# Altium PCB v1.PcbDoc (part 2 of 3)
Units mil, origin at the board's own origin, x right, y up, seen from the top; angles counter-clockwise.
Board outline 2610 x 5109 mil, 2 copper layers (Top Layer, Bottom Layer), stack 62 mil thick; 307 components, 181 nets, 763 pads, 1057 vias.
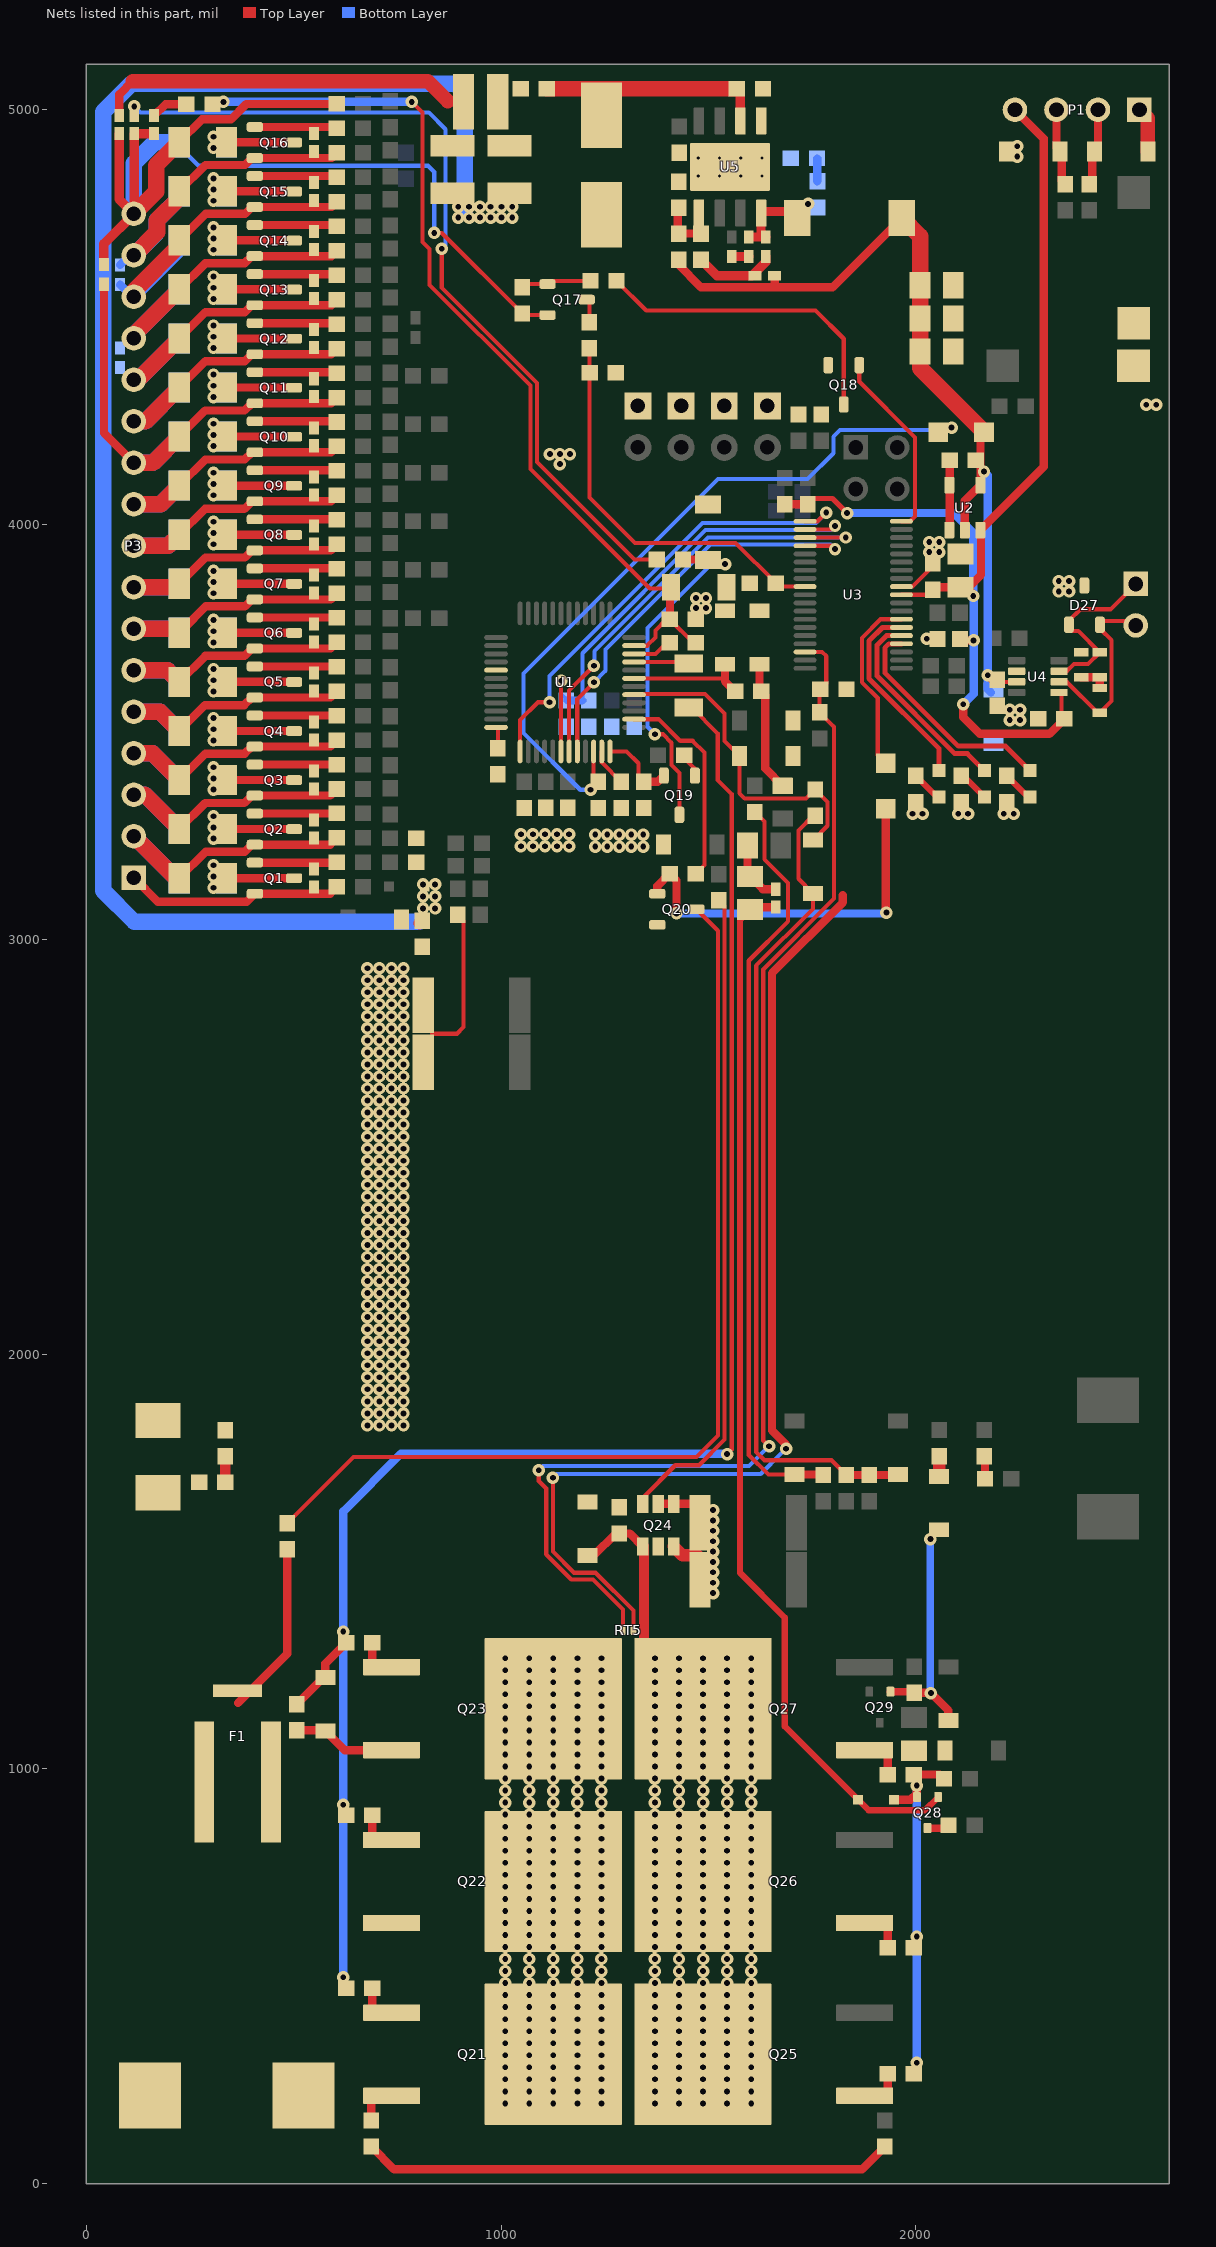
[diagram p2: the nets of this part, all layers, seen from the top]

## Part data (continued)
L2: "Inductor, Shielded Drum Core, Metal Composite, 68 μH, 0.87 A, 0.239 ohm, SMD", Manufacturer="Wurth Elektronik", Supplier Part Number 1=732-1201-1-ND, Value1="0.239 ohm", Value2=0.87A, ValueDisplayed=68μH
L3 L4 L5 L6 L7 L8: "Ferrite Bead, 600 ohm @ 100 MHz, 0.2 A, 0603", Manufacturer="Wurth Elektronik", Supplier Part Number 1=732-1583-1-ND, Value1="0.45 ohm", Value2=0.2A, ValueDisplayed="600 ohm"
Logo1: library part CMP-0074836-1, "IEC 61010-1 Caution Warning"
Logo2: library part CMP-0074847-1, "FCC_disclaimer"
Logo3: library part CMP-0074769-1
P1: "Header, 4-Pin"
P2: "Header, 2-Pin, Dual row"
P3: "Header, 17-Pin"
P4: "Header, 2-Pin"
Q1 Q2 Q3 Q4 Q5 Q6 Q7 Q8 Q9 Q10 Q11 Q12 Q13 Q14 Q15 Q16: "MOSFET, N-CH, 20 V, 2.8 A, AEC-Q101, SOT-23", Alternate Manufacturer=None, Manufacturer="Diodes Inc.", Supplier Part Number 1=DMG2302UK-7DICT-ND, Value1="0.09 ohm", Value2="1.4 nC"
Q17: "MOSFET, P-CH, -100 V, -0.6 A, SOT-23", Alternate Manufacturer=None, Manufacturer="Diodes Inc.", Supplier Part Number 1=ZXMP10A13FCT-ND, Value1="1 ohm", Value2="3.5 nC"
Q18: "MOSFET, N-CH, 100 V, 0.17 A, SOT-23", Alternate Manufacturer=None, Manufacturer="Fairchild Semiconductor", Supplier Part Number 1=BSS123NCT-ND, Value1="10 ohm", Value2="1.8 nC"
Q19: library part "ZXTN25100BFHTA, Diodes Inc.", "Transistor, NPN, 100 V, 3 A, AEC-Q101, SOT-23", Manufacturer="Diodes Inc.", Supplier Part Number 1=ZXTN25100BFHCT-ND, Value1="3 A", Value2=300
Q20: "MOSFET, N-CH, 100 V, 1.4 A, SOT-23", Alternate Manufacturer=None, Manufacturer="Diodes Inc.", Supplier Part Number 1=DMN10H220L-7DICT-ND, Value1="0.25 ohm", Value2="4.1 nC"
Q21 Q22 Q23 Q25 Q26 Q27: "MOSFET, N-CH, 100 V, 200 A, KTT0002A (TO-263-2)", Alternate Manufacturer=None, Manufacturer="Texas Instruments", Supplier Part Number 1=296-41136-1-ND, Value1="? ohm", Value2="118 nC"
Q24: "MOSFET, P-CH, -80 V, -2.1 A, SSOT-6", Alternate Manufacturer=None, Manufacturer="Fairchild Semiconductor", Supplier Part Number 1=FDC3535CT-ND, Value1="0.233 ohm", Value2="14 nC"
Q28: "MOSFET, P-CH, -20 V, -0.82 A, SOT-323", Alternate Manufacturer=None, Manufacturer="Diodes Inc.", Supplier Part Number 1=DMG1013UW-7DICT-ND, Value1="0.75 ohm", Value2="0.622 nC"
Q29: "MOSFET, N-CH, 60 V, 0.115 A, SOT-323", Alternate Manufacturer=None, Manufacturer="Diodes Inc.", Supplier Part Number 1=2N7002W-FDICT-ND, Value1="7.5 ohm", Value2="? nC"
R1 R3 R5 R7 R9 R11 R13 R15 R36 R38 R40 R42 R44: "RES, 80.6, 1%, 0.25 W, 1206", Manufacturer=Vishay-Dale, Power_W=0.25, Supplier Part Number 1=541-80.6FCT-ND, TempCo="100 ppm/C", Tolerance_%=1, Value1=1%, Value2=0.25W, Value_Code=80R6
R2 R4 R6 R8 R10 R12 R14 R16 R37 R39 R41 R43 R45 R72 R73 R74 R75 R76 R77: "RES, 80.6, 1%, 0.25 W, 1206", Manufacturer=Vishay-Dale, Power_W=0.25, Supplier Part Number 1=541-80.6FCT-ND, TempCo="100 ppm/C", Tolerance_%=1, Value1=1%, Value2=0.25W, Value_Code=80R6, ValueDisplayed=80.6
R17 R19 R21 R23 R25 R27 R29 R31 R33 R52 R54 R56 R58 R60 R61 R79 R81 R83 R87 R88 R93 R95 R96 R97 R98 R105 R106 R107 R130: "RES, 100, 1%, 0.1 W, 0603", Manufacturer=Vishay-Dale, Power_W=0.1, Supplier Part Number 1=541-100HCT-ND, TempCo="100 ppm/C", Tolerance_%=1, Value1=1%, Value2=0.1W, Value_Code=100R, ValueDisplayed=100
R18 R20 R22 R24 R26 R28 R30 R32 R51 R53 R55 R57 R59 R78 R80 R82 R84 R89 R90 R102 R103 R136: "RES, 10 k, 5%, 0.1 W, 0603", Manufacturer=Vishay-Dale, Power_W=0.1, Supplier Part Number 1=541-10KGCT-ND, TempCo="200 ppm/C", Tolerance_%=5, Value1=5%, Value2=0.1W, Value_Code=10k0, ValueDisplayed=10k
R34 R46 R47 R71 R117: "RES, 0, 5%, 0.063 W, 0402", Manufacturer=Vishay-Dale, Power_W=0.063, Supplier Part Number 1=541-0.0JCT-ND, TempCo="200 ppm/C", Tolerance_%=5, Value1=5%, Value2=0.063W, Value_Code=0000, ValueDisplayed=0
R35 R48 R49 R50 R62 R63 R64 R65 R66 R67 R68 R69 R70 R111 R115: "RES, 0, 5%, 0.1 W, 0603", Manufacturer=Vishay-Dale, Power_W=0.1, Supplier Part Number 1=541-0.0GCT-ND, TempCo="200 ppm/C", Tolerance_%=5, Value1=5%, Value2=0.1W, Value_Code=0000, ValueDisplayed=0
R85: "RES, 13.3 k, 0.5%, 0.1 W, 0603", Manufacturer="Yageo America", Power_W=0.1, TempCo="50 ppm/C", Tolerance_%=0.5, Value1=0.5%, Value2=0.1W, Value_Code=13k3, ValueDisplayed=13.3k
R86: "RES, 665 k, 0.5%, 0.1 W, 0603", Manufacturer="Yageo America", Power_W=0.1, TempCo="50 ppm/C", Tolerance_%=0.5, Value1=0.5%, Value2=0.1W, Value_Code=665k
R91: "RES, 3.3 M, 5%, 0.1 W, 0603", Manufacturer=Vishay-Dale, Power_W=0.1, Supplier Part Number 1=541-3.3MGCT-ND, TempCo="200 ppm/C", Tolerance_%=5, Value1=5%, Value2=0.1W, Value_Code=3M30, ValueDisplayed=3.3M
R92 R126: "RES, 1.0 M, 5%, 0.1 W, 0603", Manufacturer=Vishay-Dale, Power_W=0.1, Supplier Part Number 1=541-1.0MGCT-ND, TempCo="200 ppm/C", Tolerance_%=5, Value1=5%, Value2=0.1W, Value_Code=1M00, ValueDisplayed=1.0M
R94: "RES, 249, 1%, 0.1 W, 0603", Manufacturer="Yageo America", Power_W=0.1, Supplier Part Number 1=311-249HRCT-ND, TempCo="200 ppm/C", Tolerance_%=1, Value1=1%, Value2=0.1W, Value_Code=249R, ValueDisplayed=249
R99 R100 R101: "RES, 470, 1%, 0.1 W, 0603", Manufacturer="Yageo America", Power_W=0.1, Supplier Part Number 1=311-470HRCT-ND, TempCo="200 ppm/C", Tolerance_%=1, Value1=1%, Value2=0.1W, Value_Code=470R, ValueDisplayed=470
R104: "RES, 47.0 k, 1%, 0.1 W, 0603", Manufacturer="Yageo America", Power_W=0.1, Supplier Part Number 1=311-47.0KHRCT-ND, TempCo="200 ppm/C", Tolerance_%=1, Value1=1%, Value2=0.1W, Value_Code=47k0, ValueDisplayed=47.0k
R108: "RES, 10.0 k, 1%, 0.1 W, 0603", Manufacturer=Vishay-Dale, Power_W=0.1, Supplier Part Number 1=541-10.0KHCT-ND, TempCo="100 ppm/C", Tolerance_%=1, Value1=1%, Value2=0.1W, Value_Code=10k0, ValueDisplayed=10.0k
R109 R110: "RES, 60.4, 1%, 0.1 W, 0603", Manufacturer="Yageo America", Power_W=0.1, Supplier Part Number 1=311-60.4HRCT-ND, TempCo="200 ppm/C", Tolerance_%=1, Value1=1%, Value2=0.1W, Value_Code=60R4, ValueDisplayed=60.4
R112 R113: "RES, 0.002, 1%, 2 W, 2512", Manufacturer="Stackpole Electronics Inc", Power_W=2, Supplier Part Number 1=CSNL2512FT2L00CT-ND, TempCo="50 ppm/C", Tolerance_%=1, Value1=1%, Value2=2W, Value_Code=2L000, ValueDisplayed=0.002
R114 R139: "RES, 5.1 k, 5%, 0.1 W, 0603", Manufacturer=Vishay-Dale, Power_W=0.1, Supplier Part Number 1=541-5.1KGCT-ND, TempCo="200 ppm/C", Tolerance_%=5, Value1=5%, Value2=0.1W, Value_Code=5k10, ValueDisplayed=5.1k
R116: "RES, 82.5 k, 1%, 0.1 W, 0603", Manufacturer=Vishay-Dale, Power_W=0.1, Supplier Part Number 1=541-82.5KHCT-ND, TempCo="100 ppm/C", Tolerance_%=1, Value1=1%, Value2=0.1W, Value_Code=82k5, ValueDisplayed=82.5k
R118: library part RC0603FR-07499KL, "RES, 499 k, 1%, 0.1 W, 0603", Manufacturer="Yageo America", Power_W=0.1, Supplier Part Number 1=311-499KHRCT-ND, TempCo="200 ppm/C", Tolerance_%=1, Value1=1%, Value2=0.1W, Value_Code=499k
R119: library part CRCW0402523KFKED, "RES, 523 k, 1%, 0.063 W, 0402", Manufacturer=Yageo, Power_W=0.063, Supplier Part Number 1=541-523KLCT-ND, TempCo="100 ppm/C", Tolerance_%=1, Value1=1%, Value2=0.063W, Value_Code=523k
R120: "RES, 63.4 k, 1%, 0.1 W, 0603", Manufacturer=Vishay-Dale, Power_W=0.1, Supplier Part Number 1=541-63.4KHCT-ND, TempCo="100 ppm/C", Tolerance_%=1, Value1=1%, Value2=0.1W, Value_Code=63k4, ValueDisplayed=63.4k
R121: "RES, 200 k, 1%, 0.1 W, 0603", Manufacturer=Vishay-Dale, Power_W=0.1, Supplier Part Number 1=541-200KHCT-ND, TempCo="100 ppm/C", Tolerance_%=1, Value1=1%, Value2=0.1W, Value_Code=200k
R122: "RES, 200, 1%, 0.1 W, 0603", Manufacturer=Vishay-Dale, Power_W=0.1, Supplier Part Number 1=541-200HCT-ND, TempCo="100 ppm/C", Tolerance_%=1, Value1=1%, Value2=0.1W, Value_Code=200R, ValueDisplayed=200
R123: "RES, 499, 1%, 0.25 W, 1206", Manufacturer=Panasonic, Power_W=0.25, Supplier Part Number 1=P499FCT-ND, TempCo="100 ppm/C", Tolerance_%=1, Value1=1%, Value2=0.25W, Value_Code=499R, ValueDisplayed=499
R124 R131 R137: "RES, 10 M, 5%, 0.1 W, 0603", Manufacturer=Vishay-Dale, Power_W=0.1, Supplier Part Number 1=541-10MGCT-ND, TempCo="200 ppm/C", Tolerance_%=5, Value1=5%, Value2=0.1W, Value_Code=10M0, ValueDisplayed=10M
R125 R138 R140: "RES, 49.9 k, 0.1%, 0.1 W, 0603", Manufacturer="Yageo America", Power_W=0.1, TempCo="25 ppm/C", Value1=0.1%, Value2=0.1W, Value_Code=49k9, ValueDisplayed=49.9k
R127 R128: library part CRCW2512604RFKEG, "RES SMD 510 OHM 5% 1W 2512", Manufacturer=Yageo, Power_W=1, Supplier Part Number 1=541-604AFCT-ND, TempCo="100 ppm/C", Value1=5%, Value2=1W, Value_Code=510R, ValueDisplayed=510
R129: library part CRCW080556K0JNEA, "RES, 56 k, 5%, 0.125 W, 0805", Manufacturer=Yageo, Power_W=0.125, Supplier Part Number 1=541-56KACT-ND, TempCo="200 ppm/C", Tolerance_%=5, Value1=5%, Value2=0.125W, Value_Code=56k0, ValueDisplayed=56k
R132 R133 R134: "RES, 511, 1%, 0.125 W, 0805", Manufacturer=Vishay-Dale, Power_W=0.125, Supplier Part Number 1=541-511CCT-ND, TempCo="100 ppm/C", Tolerance_%=1, Value1=1%, Value2=0.125W, Value_Code=511R, ValueDisplayed=511
R135: "RES, 511, 1%, 0.1 W, 0603", Manufacturer=Vishay-Dale, Power_W=0.1, Supplier Part Number 1=541-511HCT-ND, TempCo="100 ppm/C", Tolerance_%=1, Value1=1%, Value2=0.1W, Value_Code=511R, ValueDisplayed=511
R141 R142: "RES, 20 k, 5%, 0.1 W, 0603", Manufacturer=Vishay-Dale, Power_W=0.1, Supplier Part Number 1=541-20KGCT-ND, TempCo="200 ppm/C", Tolerance_%=5, Value1=5%, Value2=0.1W, Value_Code=20k0, ValueDisplayed=20k
RT1 RT2 RT3 RT4: library part 103AT-2, "Thermistor NTC, 10.0k ohm, 1%, Disc, 5x8.4 mm", Manufacturer=Cantherm, Power_W=0.01, Supplier Part Number 1=954-103AT-2, Tolerance_%=1
RT5: library part CMP-0084566-1, "Thermistor, DEC0002A (X1SON-2)", Alternate Manufacturer="Texas Instruments", Alternate PartNumber=TMP6131DECT
S1 S2: "Switch, Tactile, SPST-NO, 0.05A, 12V, SMD", CurrentRating_mA=50, Manufacturer="C&K Components", Supplier Part Number 1=CKN10388CT-ND
U1: library part CMP-0084230-1, "Multicell Battery Monitor and Protection Family, PFB0048A (TQFP-48)", Alternate Manufacturer="Texas Instruments", Alternate PartNumber=bq76952PFBT
U2: "Single Output LDO, 150 mA, Fixed 3.3 V Output, 2.5 to 24 V Input, with Ultra-Low IQ, 5-pin SOT-23 (DBV), -40 to 125 degC, Green (RoHS & no Sb/Br)", Alternate Manufacturer="Texas Instruments", Alternate PartNumber=Equivalent, Supplier Part Number 1=296-27946-2-ND
U3: library part CMP-0084060-1, "24MHz 105C ULP Microcontroller With 32 KB FRAM, 4 KB SRAM, 44 IO, 12-bit ADC, DBT0038A (TSSOP-38)", Alternate Manufacturer="Texas Instruments", Alternate PartNumber=MSP430FR2155TDBT, Operating Temperature Range="-40 to 105 C", Rating=Catalog
U4: library part CMP-0089901-1, "Automotive High Speed CAN Transceiver", Manufacturer="Texas Instruments", Max Supply Voltage=5.5V, Min Supply Voltage=4.5V, Nominal Supply Current=5-180mA, Operating Temperature Range="-40°C to +150°C", PartNumber=TCAN1044VDDFR
U5: library part CMP-0861029-1, "100-V Input, 0.5-A Synchronous Buck DC/DC Converter with Ultra-low IQ, DDA0008E (HSOIC-8)", Alternate Manufacturer="Texas Instruments"

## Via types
v1: diameter 30, hole 14, Top Layer to Bottom Layer, 1049 vias
v2: diameter 19.68, hole 7.87, Top Layer to Bottom Layer, tented both sides, 4 vias
v3: diameter 19.68, hole 7.87, Top Layer to Bottom Layer, 4 vias

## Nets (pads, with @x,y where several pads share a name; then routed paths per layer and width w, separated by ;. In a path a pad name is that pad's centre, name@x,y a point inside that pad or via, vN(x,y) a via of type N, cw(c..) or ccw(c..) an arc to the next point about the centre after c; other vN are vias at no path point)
3V3: C36.2 C38.2 C42.1 P1.4 R102.1 R103.1 R104.2 U2.3 U3.10 U4.5 | length 2771.2
  Top Layer w10: U3.10@1965.14,3830 2027.51,3830 C38.2@2040,3842.49 C38.2@2045.51,3848 ; U4.5@2351.12,3593.94 2351.12,3537.38 C42.1@2357.5,3531
  Top Layer w12: R102.1@1739,4048.5 1752.5,4062 1799,4062 v1(1834,4027) v1@1837,4027
  Top Layer w20: R103.1@1684,4048.5 R102.1@1739,4048.5 ; C38.2@2045.51,3848 C36.2@2107,3848 C36.2@2122,3848 ; R104.2@2106.2,3723.5 2109.7,3720 v1(2139,3720) ; v1(2114,3566) 2114,3535 2154,3495 2321.5,3495 C42.1@2357.5,3531 ; v1@2139,3831 C36.2@2122,3848 ; U2.3@2155.4,3985.87 2308,4138.46 2308,4929.65 P1.4@2238.7,4998.95 ; U2.3@2157,3981.27 2157,3878 2127,3848 C36.2@2122,3848
  Bottom Layer w20: v1(1834,4027) 2091,4027 2138,3980 v1(2138,3827) 2139,3826 v1(2139,3720) 2139,3591 v1(2114,3566)
5V: C37.1 C41.1 C51.1 C52.1 C53.1 C54.1 D26.1 D28.1 L2.2 R121.2 U2.2 U2.4 U4.3 | length 2136.8
  Top Layer w10: C41.1@2196,3619 2196.54,3619.54 U4.3@2240.88,3619.54
  Top Layer w20: R121.2@1426,4637.5 1426,4627 1482,4571 1798.98,4571 L2.2@1965.98,4738 ; 1659.62,4571.38 C51.1@1659.62,4599 ; U2.2@2118,3985.87 2118,4056.73 U2.4@2155.4,4094.13 2155.4,4213.28 D28.1@2164.12,4222 ; v1(2173,3636) 2183.5,3625.5 C41.1@2196,3625.5 ; C41.1@2196,3623.02 C41.1@2196,3624
  Top Layer w40: L2.2@1965.98,4738 2010,4693.98 C54.1@2010,4576 C52.1@2010,4496 C53.1@2010,4416 2010,4376.12 D28.1@2164.12,4222
  Bottom Layer w20: v1(2164,4127) 2173,4118 v1(2173,3636) 2173,3602.47 D26.1@2181,3594.47
5V_AFE: C25.1 D28.2 U1.34 | length 1740.6
  Top Layer w10: U1.34@1223.24,3452.39 1223.24,3390.33 C25.1@1234.34,3379.23
  Bottom Layer w10: v1(1216,3360) 1191,3360 1054,3497 1054,3640 1523,4109 1739,4109 1801,4171 1801,4211 1817,4227 2080,4227 v1(2086,4233)
ALERT: U1.25 U3.20 | length 1117.4
  Top Layer w10: U1.25@1046.07,3452.39 1046.07,3528.07 1089,3571 v1(1117,3571) ; U3.20@1732.86,4007.17 1763.17,4007.17 v1(1784,4028)
  Bottom Layer w10: v1(1117,3571) 1117,3634 1486,4003 1759,4003 v1(1784,4028)
BAT+: C56.1 D31.1 F1.3 F2.2
BAT-: C55.2 D31.2 R96.1 R111.2 R112.1 R113.1 | length 359.1
  Top Layer w10: 834,2772 894,2772 910,2788 910,3044 R96.1@895.5,3058.5
  other v1: 678,1828 707,1828 736,1828 765,1828 678,1857 707,1857 736,1857 765,1857 678,1886 707,1886 736,1886 765,1886 678,1915 707,1915 736,1915 765,1915 678,1944 707,1944 736,1944 765,1944 678,1973 707,1973 736,1973 765,1973 678,2002 707,2002 736,2002 765,2002 678,2031 707,2031 736,2031 765,2031 678,2060 707,2060 736,2060 765,2060 678,2089 707,2089 736,2089 765,2089 678,2118 707,2118 736,2118 765,2118 678,2147 707,2147 736,2147 765,2147 678,2176 707,2176 736,2176 765,2176 678,2205 707,2205 736,2205 765,2205 678,2234 707,2234 736,2234 765,2234 678,2263 707,2263 736,2263 765,2263 678,2292 707,2292 736,2292 765,2292 678,2321 707,2321 736,2321 765,2321 678,2350 707,2350 736,2350 765,2350 678,2379 707,2379 736,2379 765,2379 678,2408 707,2408 736,2408 765,2408 678,2437 707,2437 736,2437 765,2437 678,2466 707,2466 736,2466 765,2466 678,2495 707,2495 736,2495 765,2495 678,2524 707,2524 736,2524 765,2524 678,2553 707,2553 736,2553 765,2553 678,2582 707,2582 736,2582 765,2582 678,2611 707,2611 736,2611 765,2611 678,2640 707,2640 736,2640 765,2640 678,2669 707,2669 736,2669 765,2669 678,2698 707,2698 736,2698 765,2698 678,2727 707,2727 736,2727 765,2727 678,2756 707,2756 736,2756 765,2756 678,2785 707,2785 736,2785 765,2785 678,2814 707,2814 736,2814 765,2814 678,2843 707,2843 736,2843 765,2843 678,2872 707,2872 736,2872 765,2872 678,2901 707,2901 736,2901 765,2901 678,2930 707,2930 736,2930 765,2930
BAT_ADC: C35.2 R85.2 R86.1 U3.28 | length 955.6
  Top Layer w10: R85.2@1213,4366.01 R86.1@1213,4424.01 ; R85.2@1213.5,4365.5 1213.5,4064.5 1323,3955 1565.5,3955 C35.2@1662.5,3858 ; C35.2@1670.81,3849.69 U3.28@1732.86,3849.69
BATS_EN: Q18.1 U3.19 | length 457.8
  Top Layer w10: Q18.1@1863.4,4383.24 1863.4,4343.6 1998,4209 1998,4019 1986.17,4007.17 U3.19@1965.14,4007.17
CANH: D27.1 P4.1 R110.1 U4.7 | length 438.1
  Top Layer w10: U4.7@2345.18,3645.8 2363.53,3645.8 2380.74,3663 2414.67,3663 R110.1@2443,3691.33 2391.33,3743 2375,3743 2368.6,3749.4 D27.1@2368.6,3757.76 2368.6,3767.6 2396,3795 2469,3795 P4.1@2530,3856 ; U4.7@2351.12,3645.13 U4.7@2357.82,3645.13
CANL: D27.2 P4.2 R109.2 U4.6 | length 456.2
  Top Layer w10: U4.6@2345.18,3620.2 2363.53,3620.2 2438.41,3545.33 R109.2@2443,3545.33 2471.5,3573.83 2471.5,3720.5 2445.16,3746.84 2445.16,3756 D27.2@2443.4,3757.76 ; U4.6@2351.12,3619.54 U4.6@2357.82,3619.54 ; D27.2@2446,3767 P4.2@2530.84,3767
Cell0: D1.2 P3.1 Q1.2 R17.1 | length 528.4
  Top Layer w20: P3.1@115,3148 173,3090 387.16,3090 Q1.2@406.76,3109.6 588.1,3109.6 R17.1@604.5,3126
Cell1: D2.2 P3.2 Q2.2 R1.1 R2.1 R19.1 | length 705.9
  Top Layer w20: R2.1@224.44,3147 288.44,3211 382.69,3211 399.49,3227.8 Q2.2@406.76,3227.8 588.37,3227.8 R19.1@604.5,3243.94
  Top Layer w40: P3.2@115,3248 R2.1@216,3147
  Bottom Layer w40: P3.2@115,3248 R1.1@216,3147
Cell2: D3.2 P3.3 Q3.2 R3.1 R4.1 R21.1 | length 707.5
  Top Layer w20: R4.1@224.44,3265.26 287.19,3328 381.49,3328 399.49,3346 Q3.2@406.76,3346 588.63,3346 R21.1@604.5,3361.87
  Top Layer w40: P3.3@115,3348 141.7,3348 R4.1@224.44,3265.26
  Bottom Layer w40: P3.3@115,3348 141.7,3348 R3.1@224.44,3265.26
Cell3: D4.2 P3.4 Q4.2 R5.1 R6.1 R23.1 | length 692.3
  Top Layer w20: R6.1@224.44,3383.51 287.93,3447 382.29,3447 399.49,3464.2 Q4.2@406.76,3464.2 588.9,3464.2 R23.1@604.5,3479.81
  Top Layer w40: P3.4@115,3448 159.96,3448 R6.1@224.44,3383.51
  Bottom Layer w40: P3.4@115,3448 159.96,3448 R5.1@224.44,3383.51
Cell4: D5.2 P3.5 Q5.2 R7.1 R8.1 R25.1 | length 677
  Top Layer w20: R8.1@224.44,3501.77 286.67,3564 381.09,3564 399.49,3582.4 Q5.2@406.76,3582.4 589.16,3582.4 R25.1@604.5,3597.74
  Top Layer w40: P3.5@115,3548 178.22,3548 R8.1@224.44,3501.77
  Bottom Layer w40: P3.5@115,3548 178.22,3548 R7.1@224.44,3501.77
Cell5: D6.2 P3.6 Q6.2 R9.1 R10.1 R27.1 | length 661.7
  Top Layer w20: R10.1@224.44,3620.03 287.42,3683 381.89,3683 399.49,3700.6 Q6.2@406.76,3700.6 589.43,3700.6 R27.1@604.5,3715.68
  Top Layer w40: P3.6@115,3648 196.47,3648 R10.1@224.44,3620.03
  Bottom Layer w40: P3.6@115,3648 196.47,3648 R9.1@224.44,3620.03
Cell6: D7.2 P3.7 Q7.2 R11.1 R12.1 R29.1 | length 619
  Top Layer w20: R12.1@234.16,3748 288.16,3802 382.69,3802 399.49,3818.8 Q7.2@406.76,3818.8 589.69,3818.8 R29.1@604.5,3833.61
  Top Layer w40: P3.7@115,3748 214.73,3748 R12.1@224.44,3738.29
  Bottom Layer w40: P3.7@115,3748 R11.1@214.73,3748
Cell7: D8.2 P3.8 Q8.2 R13.1 R14.1 R31.1 | length 633.3
  Top Layer w20: R13.1@224.44,3856.54 287.9,3920 382.49,3920 399.49,3937 Q8.2@406.76,3937 589.95,3937 R31.1@604.5,3951.55
  Top Layer w40: P3.8@115,3848 215.9,3848 R13.1@224.44,3856.54
  Bottom Layer w40: P3.8@115,3848 R14.1@215.9,3848
Cell8: D12.2 P3.9 Q9.2 R15.1 R16.1 R33.1 | length 660.4
  Top Layer w20: R16.1@224.44,3974.8 286.64,4037 381.29,4037 399.49,4055.2 Q9.2@406.76,4055.2 590.22,4055.2 R33.1@604.5,4069.48
  Top Layer w40: P3.9@115,3948 197.64,3948 R16.1@224.44,3974.8
  Bottom Layer w40: P3.9@115,3948 197.64,3948 R15.1@224.44,3974.8
Cell9: D13.2 P3.10 Q10.2 R36.1 R37.1 R52.1 | length 675.4
  Top Layer w20: R37.1@224.44,4093.06 287.39,4156 382.09,4156 399.49,4173.4 Q10.2@406.76,4173.4 590.48,4173.4 R52.1@604.5,4187.42
  Top Layer w40: P3.10@115,4048 179.39,4048 R37.1@224.44,4093.06
  Bottom Layer w40: P3.10@115,4048 179.39,4048 R36.1@224.44,4093.06
Cell10: D14.2 P3.11 Q11.2 R38.1 R39.1 R47.2 R54.1 | length 1150.6
  Top Layer w20: R47.2@43,4578.38 43,4220 P3.11@115,4148 ; R39.1@224.44,4211.32 287.13,4274 381.89,4274 399.49,4291.6 Q11.2@406.76,4291.6 590.75,4291.6 R54.1@604.5,4305.35
  Top Layer w40: P3.11@115,4148 161.13,4148 R39.1@224.44,4211.32
  Bottom Layer w40: P3.11@115,4148 161.13,4148 R38.1@224.44,4211.32
Cell11: D15.2 P3.12 Q12.2 R40.1 R41.1 R56.1 | length 705.3
  Top Layer w20: R41.1@224.44,4329.57 287.87,4393 382.69,4393 399.49,4409.8 Q12.2@406.76,4409.8 591.01,4409.8 R56.1@604.5,4423.29
  Top Layer w40: P3.12@115,4248 142.87,4248 R41.1@224.44,4329.57
  Bottom Layer w40: P3.12@115,4248 142.87,4248 R40.1@224.44,4329.57
Cell12: D16.2 P3.13 Q13.2 R34.1 R42.1 R43.1 R58.1 | length 720.3
  Top Layer w20: R43.1@224.44,4447.83 287.61,4511 382.49,4511 399.49,4528 Q13.2@406.76,4528 591.28,4528 R58.1@604.5,4541.22
  Top Layer w40: P3.13@115,4348 124.61,4348 R43.1@224.44,4447.83
  Bottom Layer w40: P3.13@115,4348 124.61,4348 R42.1@224.44,4447.83
Cell13: D17.2 P3.14 Q14.2 R34.2 R44.1 R45.1 R60.1 | length 745.5
  Top Layer w20: R45.1@224.44,4566.09 287.36,4629 382.29,4629 399.49,4646.2 Q14.2@406.76,4646.2 591.54,4646.2 R60.1@604.5,4659.16
  Top Layer w40: P3.14@115,4448 115,4456.64 R45.1@224.44,4566.09
  Bottom Layer w40: P3.14@115,4448 115,4456.64 R44.1@224.44,4566.09
Cell14: D18.2 P3.15 Q15.2 R71.1 R72.1 R73.1 R79.1 | length 827
  Top Layer w20: R73.1@224.44,4684.34 288.1,4748 383.09,4748 399.49,4764.4 Q15.2@406.76,4764.4 591.81,4764.4 R79.1@604.5,4777.1
  Top Layer w40: P3.15@115,4548 115,4562 224.44,4671.44 R73.1@224.44,4684.34
  Bottom Layer w20: R71.1@82,4577.38 111.38,4548 P3.15@115,4548
  Bottom Layer w40: P3.15@115,4548 115,4555.42 224.44,4664.86 R72.1@224.44,4684.34
Cell15: D19.2 P3.16 Q16.2 R71.2 R74.1 R75.1 R81.1 | length 844.7
  Top Layer w20: R74.1@224.44,4802.6 287.84,4866 382.89,4866 399.49,4882.6 Q16.2@406.76,4882.6 592.07,4882.6 R81.1@604.5,4895.03
  Top Layer w40: P3.16@115,4648 171,4704 171,4733 224.44,4786.44 R74.1@224.44,4802.6
  Bottom Layer w20: R71.2@82,4624.62 105.38,4648 P3.16@115,4648
  Bottom Layer w40: P3.16@115,4648 170.53,4703.53 170.53,4732.53 R75.1@224.44,4786.44
Cell16: D11.2 D20.2 D30.2 P3.17 Q17.2 R47.1 R76.1 R77.1 R83.1 R92.2 | length 2646
  Top Layer w10: v1(839,4702) 857.13,4702 R92.2@1051.3,4507.83 1055.2,4503.92 Q17.2@1112.06,4503.92
  Top Layer w20: R76.1@224.44,4920.86 279.59,4976 349,4976 386,5013 R83.1@604.5,5013
  Top Layer w23: R47.1@43,4625.62 43,4676 P3.17@115,4748 80,4783 D30.2@80,4941.35 ; P3.17@116,4749 D20.2@116,4941.35 D11.2@164,4941.35
  Top Layer w40: P3.17@115,4748 116,4749 169,4802 169,4865.41 R76.1@224.44,4920.86
  Bottom Layer w10: P3.17@115,4748 P3.17@118,4745 ; R77.1@224.44,4920.86 224.44,4910.56 271,4864 824,4864 839,4849 v1(839,4702)
  Bottom Layer w40: P3.17@115,4748 115,4870 165.86,4920.86 R77.1@224.44,4920.86
CHG: R123.1 U1.45 | length 127.5
  Top Layer w10: U1.45@1320.68,3667.94 R123.1@1448.2,3667.94
DCHG: U1.31 U3.22 | length 1082.8
  Top Layer w10: U1.31@1164.18,3452.39 1164.18,3599.18 v1(1224,3659) ; U3.22@1732.86,3967.8 v1@1830.8,3967.8
  Bottom Layer w10: v1@1225,3660 1225,3694 1499,3968 v1(1831,3968)
DDSG: U1.32 U3.23 | length 1011.7
  Top Layer w10: U1.32@1183.87,3452.39 1183.87,3578.87 v1(1224,3619) ; U3.23@1732.86,3948.11 1796.89,3948.11 v1(1805,3940)
  Bottom Layer w10: v1(1224,3619) 1252,3647 1252,3698 1505,3951 1794,3951 v1(1805,3940)
DSG: D35.1 R130.1 U1.43 | length 297.9
  Top Layer w10: U1.43@1320.68,3628.57 1532.93,3628.57 1540,3621.5
  Top Layer w20: D35.1@1540,3662.53 1540,3621.5 R130.1@1564.5,3597
FETOFF: C23.1 R89.2 U1.30 U3.21 | length 1176.6
  Top Layer w10: U1.30@1144.5,3452.39 v1@1144.5,3622.5 ; U3.21@1732.86,3987.48 1796.48,3987.48 v1(1805,3996)
  Bottom Layer w10: v1(1145,3623) 1145,3590.99 C23.1@1161,3574.99 ; R89.2@1196,3583.99 1196,3689 1493,3986 1795,3986 v1(1805,3996)
  Bottom Layer w20: C23.1@1161,3574.99 R89.2@1196,3574.99
Fuse: D29.1 Q20.1 R114.2 | length 915.6
  Top Layer w20: Q20.1@1376.76,3109.4 1376.76,3128.25 R114.2@1406.5,3158 1423,3141.5 v1(1423,3062) ; v1@1927,3066 D29.1@1927,3313.88
  Bottom Layer w20: v1(1423,3062) v1@1927,3062
  other v1: 1929,3064
FUSE_AFE: R114.1 U1.38 | length 503.2
  Top Layer w10: U1.38@1320.68,3530.15 1379.85,3530.15 1432,3478 1462,3478 1490.21,3449.79 1490.21,3178.72 R114.1@1469.5,3158
FUSE_MCU: D29.2 U3.7 | length 439.3
  Top Layer w10: D29.2@1927,3424.12 1908,3443.12 1908,3581 1870,3619 1870,3726.04 1914.9,3770.94 U3.7@1965.14,3770.94
GND: C1.2 C9.2 C15.1 C16.1 C17.2 C19.2 C23.2 C24.2 C25.2 C26.2 C27.2 C28.2 C29.2 C30.2 C31.2 C34.2 C35.1 C36.1 C37.2 C38.1 C39.2 C40.2 C41.2 C42.2 C43.1 C44.2 C45.2 C46.2 C47.2 C48.2 C52.2 C53.2 C54.2 D9.2 D10.2 D21.2 D22.2 D26.2 D27.3 D33.2 D35.2 D36.2 D41.2 D43.2 P1.1 Q18.2 Q20.2 R85.1 R89.1 R90.1 R99.1 R100.1 R101.1 R111.1 R116.1 R120.1 RT1.1 RT2.1 RT3.1 RT4.1 RT5.1 S1.2 S2.2 U1.17 U2.1 U2.5 U3.11 U4.2 U5.1 U5.9@1552,4861 | length 6721
  Top Layer w10: v1(1125,1702) 1125,1524 1176,1473 1228,1473 1319.32,1381.68 RT5.1@1319.32,1334.51 ; U3.11@1965.14,3849.69 1991.68,3849.69 C38.1@2040,3898
  Top Layer w20: v1(1687,1772) 1687,1782 1653,1816 1653,2918 1823.7,3088.7 1823.7,3106 ; C40.2@1827,3596.5 C40.2@1832.5,3602 ; U2.1@2081.5,3986.77 C37.2@2081.5,4154
  Top Layer w30: R111.1@803.5,3038 R111.1@810,3044.5
  Top Layer w35: P1.1@2538.7,4998.95 2559.17,4978.48 D21.2@2559.17,4897.95
  Bottom Layer w10: v1(1125,1702) 1134,1711 1626,1711 1675,1760
  Bottom Layer w40: 802.5,3042 116,3042 41,3117 41,4994 109,5062 890,5062 913,5039 v1@913,4757
  other v1: 812,3074 841,3074 812,3103 841,3103 812,3132 841,3132 1227,3223 1256,3223 1285,3223 1314,3223 1343,3223 1048,3224 1077,3224 1106,3224 1135,3224 1164,3224 1227,3252 1256,3252 1285,3252 1314,3252 1343,3252 1048,3253 1077,3253 1106,3253 1135,3253 1164,3253 1992,3302.21 2016,3302.21 2101.82,3302.21 2125.82,3302.21 2211.64,3302.21 2235.64,3302.21 2226,3528 2251,3528 2226,3553 2251,3553 2026,3724 1470,3798 1494,3798 1470,3822 1494,3822 2344,3838 2369,3838 2344,3863 2369,3863 2032,3933 2056,3933 2032,3957 2056,3957 1142,4145 1118,4169 1142,4169 1166,4169 2555,4288 2579,4288 897,4739 923,4739 949,4739 975,4739 1001,4739 1027,4739 897,4765 923,4765 949,4765 975,4765 1001,4765 1027,4765 2244,4886 2244,4911
  other v2: 1475.23,4839.35 1628.77,4839.35 1475.23,4882.65 1628.77,4882.65
  other v3: 1526.41,4839.35 1577.59,4839.35 1526.41,4882.65 1577.59,4882.65
LD: D41.1 D44.2 R138.1 U1.41 | length 789.7
  Top Layer w10: U1.41@1320.68,3589.2 1320.68,3590.5 1491.5,3590.5 1538.21,3543.79 1538.21,3477.32 D41.1@1574.53,3441 1574.53,3351.47 1587.32,3338.69 1735.19,3338.69 R138.1@1757,3360.5 1786.7,3330.8 1786.7,3273.26 D44.2@1752.91,3239.47
LED1: D23.2 U3.6 | length 474.2
  Top Layer w12: U3.6@1965.14,3751.26 1919.26,3751.26 1887,3719 1887,3628 2055.18,3459.82 D23.2@2055.18,3405.99
LED2: D24.2 U3.5 | length 496.4
  Top Layer w12: U3.5@1965.14,3731.57 1929.12,3731.57 1906,3708.46 1906,3634.46 2093.46,3447 2123.99,3447 D24.2@2165,3405.99
LED3: D25.2 U3.4 | length 551.8
  Top Layer w12: U3.4@1965.14,3711.89 1934.89,3711.89 1925,3702 1925,3642 2102,3465 2215.81,3465 D25.2@2274.82,3405.99
NetC15_2: C15.2 C16.2 C18.2 R61.2 U1.47 | length 2183.9
  Top Layer w10: v1(785,5018) 811,4992 811,4680 828,4663 828,4577 1071,4334 1071,4133 1358.57,3845.43 C15.2@1407.5,3845.43 ; U1.47@1320.68,3707.31 1352.32,3707.31 1372,3727 1372,3744 1399,3771 C16.2@1406.5,3771 C18.2@1463.5,3714 ; C16.2@1407.5,3782 C16.2@1410,3782
  Top Layer w20: C16.2@1407.5,3782 C15.2@1407.5,3845.43
  Bottom Layer w20: v1(331,5018) 780,5018 v1@785,5013
NetC18_1: C18.1 U1.46 | length 89.2
  Top Layer w10: U1.46@1320.68,3687.63 1372.63,3687.63 C18.1@1399,3714
NetC19_1: C19.1 U1.24 | length 52
  Top Layer w10: U1.24@988,3510.46 992.34,3506.13 C19.1@992.34,3460.23
NetC26_1: C26.1 U1.35 | length 92.5
  Top Layer w10: U1.35@1242.92,3452.39 1242.92,3425.53 1289.23,3379.23 C26.1@1289.34,3379.23
NetC27_1: C27.1 Q19.2 U1.36 | length 185.1
  Top Layer w10: U1.36@1262.61,3452.39 1302.61,3452.39 1331,3424 1331,3392.23 C27.1@1344,3379.23
  Top Layer w20: C27.1@1344,3379.23 1377.58,3379.23 Q19.2@1392.6,3394.24
NetC29_1: C29.1 Q19.3 R94.1 | length 804.9
  Top Layer w10: v1(1371,3494) 1390,3494 1410.81,3473.19 1410.81,3419.74 1430,3400.55 Q19.3@1430,3299.76
  Top Layer w20: R94.1@1438.5,3915 1498.07,3915 C29.1@1499,3914.07
  Bottom Layer w10: v1(1371,3494) 1353,3512 1353,3750 1507,3904 v1(1540,3904)
NetC40_1: C40.1 R108.1 RT5.2 U3.36 | length 3135.8
  Top Layer w10: v1(1091,1720) 1091,1694 1109,1676 1109,1517.37 1169.37,1457 1221.37,1457 1293.72,1384.65 RT5.2@1293.72,1334.51 ; v1(1646,1778) 1632,1792 1632,2927 1802.7,3097.7 1802.7,3511.8 R108.1@1768,3546.5 1768,3600.5 C40.1@1769.5,3602 1784,3616.5 1784,3682 1773.8,3692.2 U3.36@1732.86,3692.2
  Bottom Layer w10: v1(1091,1720) 1101,1730 1598,1730 v1(1646,1778)
NetC43_2: C43.2 R109.1 R110.2 | length 71
  Top Layer w20: C43.2@2398,3631.33 R110.2@2443,3631.33 R109.1@2443,3605.33
NetC44_1: C44.1 D30.1 L1.1 | length 876.5
  Top Layer w20: D30.1@80,4984.65 80,5036 112,5068
  Top Layer w35: 112,5068 824,5068 872,5020
NetC45_1: C45.1 L1.2 R115.1
NetC46_1: C46.1 C47.1 R115.2 U5.2 | length 530.2
  Top Layer w23: U5.2@1577,4968.28 C46.1@1577,5044.5
  Top Layer w37: R115.2@1110.5,5050 C46.1@1564.5,5050
NetC48_1: C48.1 R118.1 | length 55
  Bottom Layer w20: R118.1@1762,4826.5 C48.1@1762,4881.5
NetC49_1: C49.1 R117.2 | length 41
  Top Layer w22: R117.2@1556,4645.38 C49.1@1597,4645.38
NetC49_2: C49.2 L2.1 R118.2 R119.1 U5.8 | length 177.9
  Top Layer w22: C49.2@1597,4692.62 R119.1@1638,4692.62 1627,4703.62 1627,4753.72 1688,4753.72 L2.1@1698.3,4753.72
  other v1: 1740,4772
NetC50_1: C50.1 C51.2 R119.2 | length 199
  Top Layer w22: C50.1@1482,4637.5 1520.5,4599 1605,4599 1638,4632 R119.2@1638,4645.38
NetC50_2: C50.2 R120.2 R121.1 U5.5 | length 118
  Top Layer w20: R120.2@1426,4762.5 1426,4700.5 C50.2@1482,4700.5
NetC55_1: C55.1 C56.2 | length 62.5
  Top Layer w25: C56.2@335,1691 C55.1@335,1753.5
NetC57_1: C57.1 C58.2 | length 1283.4
  Top Layer w20: C57.1@687.34,90.01 742.35,35 1870.19,35 C58.2@1925.2,90.01
NetC57_2: C57.2 D32.2 F1.1 F2.1 Q21.3 Q22.3 Q23.3 R124.2 | length 306.5
  Top Layer w20: R124.2@507.52,1093.01 D32.2@575.55,1093.01 ; D32.2@576.52,1092.04 623.16,1045.4 679.52,1045.4 Q23.3@736.3,1045.4 ; C57.2@687.34,153 Q21.3@687.34,212.4
NetC59_1: C59.1 C60.2 | length 55
  Top Layer w20: C60.2@2166.5,1699 C59.1@2166.5,1754.02
NetD1_1: D1.1 Q1.1 R18.1 | length 198
  Top Layer w20: Q1.1@406.76,3184.4 603.94,3184.4 R18.1@604.5,3184.97
NetD2_1: D2.1 Q2.1 R20.1 | length 197.4
  Top Layer w20: Q2.1@406.76,3302.6 R20.1@604.2,3302.6
NetD3_1: D3.1 Q3.1 R22.1 | length 197.7
  Top Layer w20: Q3.1@406.76,3420.8 R22.1@604.5,3420.84
NetD4_1: D4.1 Q4.1 R24.1 | length 197.5
  Top Layer w20: Q4.1@406.76,3539 R24.1@604.28,3539
NetD5_1: D5.1 Q5.1 R26.1 | length 197.3
  Top Layer w20: Q5.1@406.76,3657.2 R26.1@604.01,3657.2
NetD6_1: D6.1 Q6.1 R28.1 | length 197
  Top Layer w20: Q6.1@406.76,3775.4 R28.1@603.75,3775.4
NetD7_1: D7.1 Q7.1 R30.1 | length 196.7
  Top Layer w20: Q7.1@406.76,3893.6 R30.1@603.48,3893.6
NetD8_1: D8.1 Q8.1 R32.1 | length 196.5
  Top Layer w20: Q8.1@406.76,4011.8 R32.1@603.22,4011.8
NetD11_1: D11.1 R61.1 | length 88.8
  Top Layer w20: D11.1@164,4984.65 191.35,5012 R61.1@241.5,5012
NetD12_1: D12.1 Q9.1 R51.1 | length 196.2
  Top Layer w20: Q9.1@406.76,4130 R51.1@602.95,4130
NetD13_1: D13.1 Q10.1 R53.1 | length 195.9
  Top Layer w20: Q10.1@406.76,4248.2 R53.1@602.69,4248.2
NetD14_1: D14.1 Q11.1 R55.1 | length 198.6
  Top Layer w20: Q11.1@406.76,4366.4 602.42,4366.4 R55.1@604.5,4364.32
NetD15_1: D15.1 Q12.1 R57.1 | length 195.4
  Top Layer w20: Q12.1@406.76,4484.6 R57.1@602.16,4484.6
NetD16_1: D16.1 Q13.1 R59.1 | length 195.1
  Top Layer w20: Q13.1@406.76,4602.8 R59.1@601.89,4602.8
NetD17_1: D17.1 Q14.1 R78.1 | length 194.9
  Top Layer w20: Q14.1@406.76,4721 R78.1@601.63,4721
NetD18_1: D18.1 Q15.1 R80.1 | length 194.6
  Top Layer w20: Q15.1@406.76,4839.2 R80.1@601.37,4839.2
NetD19_1: D19.1 Q16.1 R82.1 | length 194.3
  Top Layer w20: Q16.1@406.76,4957.4 R82.1@601.1,4957.4
NetD20_1: D20.1 R94.2 | length 2059.6
  Top Layer w10: v1(857,4664) 857,4570.63 1087,4340.63 1087,4150 1322,3915 R94.2@1375.5,3915
  Bottom Layer w10: v1(116,5007) 131,4992 826,4992 866,4952 866,4673 v1(857,4664)
NetD21_1: D21.1 P1.2 R97.2 | length 177.7
  Top Layer w20: R97.2@2424.7,4826.68 2424.7,4892.42 D21.1@2430.23,4897.95 D21.1@2437.7,4905.42 ; D21.1@2438.7,4905.42 P1.2@2438.7,4998.95
NetD22_1: D22.1 P1.3 R98.2 | length 172.7
  Top Layer w20: D22.1@2338.7,4907.42 P1.3@2338.7,4998.95 ; D22.1@2347.17,4897.95 2351.7,4902.48 R98.2@2351.7,4827.75
NetD23_1: D23.1 R99.2 | length 76.6
  Top Layer w15: R99.2@1999.54,3393.69 2050.23,3343 D23.1@2055.18,3343
NetD24_1: D24.1 R100.2 | length 76.6
  Top Layer w15: R100.2@2109.36,3393.69 2114.31,3393.69 D24.1@2165,3343
NetD25_1: D25.1 R101.2 | length 76.6
  Top Layer w15: R101.2@2219.18,3393.69 2269.87,3343 D25.1@2274.82,3343
NetD32_1: D32.1 L3.1 L4.1 L5.1 R123.2 R124.1 | length 4152.2
  Top Layer w10: R123.2@1452,3557.85 1460.15,3557.85 1522.21,3495.79 1522.21,3384 1556,3350.21 1556,1770 v1(1545,1759)
  Top Layer w20: R124.1@507.52,1156 D32.1@572.49,1220.98 ; D32.1@576.52,1220.98 576.52,1254 L5.1@627.02,1304.51
  Bottom Layer w20: v1(620,498) v1(620,914) v1(620,1331) 620,1621 759,1760 v1@1544,1760
NetD34_1: D34.1 Q21.2 Q22.2 Q23.2 Q24.4 Q25.2 Q26.2 Q27.2 R126.2 | length 759
  Top Layer w20: D34.1@1208.48,1514 1223.01,1514 1276.66,1567.64 R126.2@1285.11,1567.64 1310.59,1567.64 Q24.4@1341.6,1536.64
  Top Layer w25: Q24.4@1341.6,1536.64 1344.7,1536.64 1344.7,1304.2 1344,1304.2 Q27.2@1344,1145.5
  Top Layer w30: Q27.2@1348,1283.98 Q27.2@1486.48,1145.5
  other v1: 1010,194 1068,194 1126,194 1184,194 1242,194 1371,194 1429,194 1487,194 1545,194 1603,194 1010,223 1068,223 1126,223 1184,223 1242,223 1371,223 1429,223 1487,223 1545,223 1603,223 1010,252 1068,252 1126,252 1184,252 1242,252 1371,252 1429,252 1487,252 1545,252 1603,252 1010,281 1068,281 1126,281 1184,281 1242,281 1371,281 1429,281 1487,281 1545,281 1603,281 1010,310 1068,310 1126,310 1184,310 1242,310 1371,310 1429,310 1487,310 1545,310 1603,310 1010,339 1068,339 1126,339 1184,339 1242,339 1371,339 1429,339 1487,339 1545,339 1603,339 1010,368 1068,368 1126,368 1184,368 1242,368 1371,368 1429,368 1487,368 1545,368 1603,368 1010,397 1068,397 1126,397 1184,397 1242,397 1371,397 1429,397 1487,397 1545,397 1603,397 1010,426 1068,426 1126,426 1184,426 1242,426 1371,426 1429,426 1487,426 1545,426 1603,426 1010,455 1068,455 1126,455 1184,455 1242,455 1371,455 1429,455 1487,455 1545,455 1603,455 1010,484 1068,484 1126,484 1184,484 1242,484 1371,484 1429,484 1487,484 1545,484 1603,484 1010,513 1068,513 1126,513 1184,513 1242,513 1371,513 1429,513 1487,513 1545,513 1603,513 1010,542 1068,542 1126,542 1184,542 1242,542 1371,542 1429,542 1487,542 1545,542 1603,542 1010,571 1068,571 1126,571 1184,571 1242,571 1371,571 1429,571 1487,571 1545,571 1603,571 1010,600 1068,600 1126,600 1184,600 1242,600 1371,600 1429,600 1487,600 1545,600 1603,600 1010,629 1068,629 1126,629 1184,629 1242,629 1371,629 1429,629 1487,629 1545,629 1603,629 1010,658 1068,658 1126,658 1184,658 1242,658 1371,658 1429,658 1487,658 1545,658 1603,658 1010,687 1068,687 1126,687 1184,687 1242,687 1371,687 1429,687 1487,687 1545,687 1603,687 1010,716 1068,716 1126,716 1184,716 1242,716 1371,716 1429,716 1487,716 1545,716 1603,716 1010,745 1068,745 1126,745 1184,745 1242,745 1371,745 1429,745 1487,745 1545,745 1603,745 1010,774 1068,774 1126,774 1184,774 1242,774 1371,774 1429,774 1487,774 1545,774 1603,774 1010,803 1068,803 1126,803 1184,803 1242,803 1371,803 1429,803 1487,803 1545,803 1603,803 1010,832 1068,832 1126,832 1184,832 1242,832 1371,832 1429,832 1487,832 1545,832 1603,832 1010,861 1068,861 1126,861 1184,861 1242,861 1371,861 1429,861 1487,861 1545,861 1603,861 1010,890 1068,890 1126,890 1184,890 1242,890 1371,890 1429,890 1487,890 1545,890 1603,890 1010,919 1068,919 1126,919 1184,919 1242,919 1371,919 1429,919 1487,919 1545,919 1603,919 1010,948 1068,948 1126,948 1184,948 1242,948 1371,948 1429,948 1487,948 1545,948 1603,948 1010,977 1068,977 1126,977 1184,977 1242,977 1371,977 1429,977 1487,977 1545,977 1603,977 1010,1006 1068,1006 1126,1006 1184,1006 1242,1006 1371,1006 1429,1006 1487,1006 1545,1006 1603,1006 1010,1035 1068,1035 1126,1035 1184,1035 1242,1035 1371,1035 1429,1035 1487,1035 1545,1035 1603,1035 1010,1064 1068,1064 1126,1064 1184,1064 1242,1064 1371,1064 1429,1064 1487,1064 1545,1064 1603,1064 1010,1093 1068,1093 1126,1093 1184,1093 1242,1093 1371,1093 1429,1093 1487,1093 1545,1093 1603,1093 1010,1122 1068,1122 1126,1122 1184,1122 1242,1122 1371,1122 1429,1122 1487,1122 1545,1122 1603,1122 1010,1151 1068,1151 1126,1151 1184,1151 1242,1151 1371,1151 1429,1151 1487,1151 1545,1151 1603,1151 1010,1180 1068,1180 1126,1180 1184,1180 1242,1180 1371,1180 1429,1180 1487,1180 1545,1180 1603,1180 1010,1209 1068,1209 1126,1209 1184,1209 1242,1209 1371,1209 1429,1209 1487,1209 1545,1209 1603,1209 1010,1238 1068,1238 1126,1238 1184,1238 1242,1238 1371,1238 1429,1238 1487,1238 1545,1238 1603,1238 1010,1267 1068,1267 1126,1267 1184,1267 1242,1267 1371,1267 1429,1267 1487,1267 1545,1267 1603,1267
NetD34_2: D34.2 Q24.3 R125.2 R126.1 | length 1575.7
  Top Layer w10: Q24.3@1341.6,1639 1341.6,1653.6 1420,1732 1477,1732 1539,1794 1539,3079.72 R125.2@1525,3093.72
NetD36_1: D36.1 R130.2 R132.1 | length 310
  Top Layer w20: R130.2@1623,3601.5 D36.1@1623,3662.53 ; R130.2@1627.5,3597 1637,3587.5 1637,3411.37 R132.1@1679,3369.37
NetD37_1: D37.1 D38.2 Q28.1 R129.2 | length 2554
  Top Layer w15: R129.2@1600,3071.2 1576,3047.2 1576,1473 1684,1365 1684,1102.69 D38.2@1860.69,926 1886,900.69 2021.88,900.69 Q28.1@2053.59,932.4
  Top Layer w20: R129.2@1600,3071.2 1605.85,3077.05 D37.1@1662,3077.05
NetD37_2: D37.2 R129.1 R133.1 | length 151.6
  Top Layer w20: R133.1@1594,3225.5 1594,3157.2 R129.1@1600,3151.2 1630.85,3120.35 D37.2@1662,3120.35
NetD38_1: D38.1 D39.1 L6.1 L7.1 L8.1 Q28.2 R131.1 R134.1 | length 824.7
  Top Layer w20: D38.1@1947.31,926 1987,926 2002,941 v1(2002,960) ; L8.1@1995.02,986.51 2057,986.51 R131.1@2067.5,976
  Bottom Layer w20: v1(2002,292) v1(2002,596) v1(2002,960)
NetD40_1: D40.1 D42.1 Q29.1 R137.2 | length 548.6
  Top Layer w18: Q29.1@1938.59,1186.4 R137.2@1993.1,1186.4
  Top Layer w20: R137.2@1996,1183.5 2035.5,1183.5 v1(2036,1183) 2078,1141 D40.1@2078,1116.53
  Bottom Layer w18: v1@2035,1184 v1(2035,1554)
NetD42_2: D42.2 R136.2 | length 48.6
  Top Layer w30: D42.2@2056,1705.47 R136.2@2056,1754.02
NetD44_1: D44.1 D46.1 R138.2 R141.1 R142.1 | length 1989
  Top Layer w10: R138.2@1757,3297.5 1752.45,3297.5 1716.98,3262.04 1716.98,3145.55 D44.1@1752,3110.53 1752,3073 1615,2936 1615,1764 1635,1744 1796.5,1744 R142.1@1832,1708.5
  Top Layer w20: R142.1@1832,1708.5 R141.1@1887,1708.5 D46.1@1957,1708.5
NetD45_1: D45.1 R139.2 R140.1 | length 1822.7
  Top Layer w10: R139.2@1612,3306.5 1635,3283.5 1635,3192.44 1692,3135.44 1692,3043 1597,2948 1597,1757 1644.47,1709.53 D45.1@1707,1709.53
  Top Layer w20: D45.1@1707,1709.53 1777,1709.53 R140.1@1777,1708.5
NetF1_2: F1.2 R122.1 | length 419.8
  Top Layer w20: 366,1159 485,1278 R122.1@485,1529.5
NetL3_2: L3.2 Q21.1 | length 59.1
  Top Layer w20: Q21.1@690.02,412.4 L3.2@690.02,471.51
NetL4_2: L4.2 Q22.1 | length 59.1
  Top Layer w20: Q22.1@690.02,828.9 L4.2@690.02,888.01
NetL5_2: L5.2 Q23.1 | length 56.5
  Top Layer w20: Q23.1@690.02,1248.02 L5.2@690.02,1304.51
NetL6_2: L6.2 Q25.1 | length 49.5
  Top Layer w20: Q25.1@1932.02,215.98 L6.2@1932.02,265.51
NetL7_2: L7.2 Q26.1 | length 52.5
  Top Layer w20: L7.2@1932.02,569.51 Q26.1@1932.02,622.02
NetL8_2: L8.2 Q27.1 | length 90.3
  Top Layer w20: Q27.1@1876.24,1045.5 Q27.1@1907.5,1045.5 ; L8.2@1932.02,986.51 Q27.1@1932.02,1045.52
NetQ1_3: Q1.3 R1.2 R2.2 | length 162.6
  Top Layer w20: R2.2@338.62,3147 Q1.3@501.24,3147
  other v1: 307,3124 307,3151 307,3178
NetQ2_3: Q2.3 R3.2 R4.2 | length 162.6
  Top Layer w20: R4.2@338.62,3265.26 Q2.3@501.19,3265.26
  other v1: 307,3242.26 307,3269.26 307,3296.26
NetQ3_3: Q3.3 R5.2 R6.2 | length 162.5
  Top Layer w20: R6.2@338.62,3383.51 Q3.3@501.13,3383.51
  other v1: 307,3360.51 307,3387.51 307,3414.51
NetQ4_3: Q4.3 R7.2 R8.2 | length 162.5
  Top Layer w20: R8.2@338.62,3501.77 Q4.3@501.07,3501.77
  other v1: 307,3478.77 307,3505.77 307,3532.77
NetQ5_3: Q5.3 R9.2 R10.2 | length 162.4
  Top Layer w20: R10.2@338.62,3620.03 Q5.3@501.01,3620.03
  other v1: 307,3597.03 307,3624.03 307,3651.03
NetQ6_3: Q6.3 R11.2 R12.2 | length 162.3
  Top Layer w20: R12.2@338.62,3738.29 Q6.3@500.96,3738.29
  other v1: 307,3715.29 307,3742.29 307,3769.29
NetQ7_3: Q7.3 R13.2 R14.2 | length 162.3
  Top Layer w20: R13.2@338.62,3856.54 Q7.3@500.9,3856.54
  other v1: 307,3833.54 307,3860.54 307,3887.54
NetQ8_3: Q8.3 R15.2 R16.2 | length 162.2
  Top Layer w20: R16.2@338.62,3974.8 Q8.3@500.84,3974.8
  other v1: 307,3951.8 307,3978.8 307,4005.8
NetQ9_3: Q9.3 R36.2 R37.2 | length 162.2
  Top Layer w20: R37.2@338.62,4093.06 Q9.3@500.79,4093.06
  other v1: 307,4070.06 307,4097.06 307,4124.06
NetQ10_3: Q10.3 R38.2 R39.2 | length 162.1
  Top Layer w20: R39.2@338.62,4211.32 Q10.3@500.73,4211.32
  other v1: 307,4188.32 307,4215.32 307,4242.32
NetQ11_3: Q11.3 R40.2 R41.2 | length 162.1
  Top Layer w20: R41.2@338.62,4329.57 Q11.3@500.67,4329.57
  other v1: 307,4306.57 307,4333.57 307,4360.57
NetQ12_3: Q12.3 R42.2 R43.2 | length 162
  Top Layer w20: R43.2@338.62,4447.83 Q12.3@500.61,4447.83
  other v1: 307,4424.83 307,4451.83 307,4478.83
NetQ13_3: Q13.3 R44.2 R45.2 | length 161.9
  Top Layer w20: R45.2@338.62,4566.09 Q13.3@500.56,4566.09
  other v1: 307,4543.09 307,4570.09 307,4597.09
NetQ14_3: Q14.3 R72.2 R73.2 | length 161.9
  Top Layer w20: R73.2@338.62,4684.34 Q14.3@500.5,4684.34
  other v1: 307,4661.34 307,4688.34 307,4715.34
NetQ15_3: Q15.3 R74.2 R75.2 | length 161.8
  Top Layer w20: R74.2@338.62,4802.6 Q15.3@500.44,4802.6
  other v1: 307,4779.6 307,4806.6 307,4833.6
NetQ16_3: Q16.3 R76.2 R77.2 | length 161.8
  Top Layer w20: R76.2@338.62,4920.86 Q16.3@500.38,4920.86
  other v1: 307,4907 307,4934
NetQ17_1: Q17.1 R91.2 R92.1 | length 170.7
  Top Layer w10: R92.1@1051.3,4570.82 1059.2,4578.72 Q17.1@1112.06,4578.72 1119.83,4586.5 R91.2@1215.5,4586.5
NetQ17_3: Q17.3 R86.2 | length 47.9
  Top Layer w10: R86.2@1213,4487 Q17.3@1213,4534.87
NetQ18_3: Q18.3 R91.1 | length 763.5
  Top Layer w10: R91.1@1278.5,4586.5 1350,4515 1758,4515 1826,4447 Q18.3@1826,4288.76
NetQ19_1: Q19.1 R93.2 | length 61.8
  Top Layer w10: R93.2@1437.5,3446 1437.5,3440.5 1467.4,3410.6 Q19.1@1467.4,3396.6
NetQ20_3: Q20.3 R122.2 | length 2415
  Top Layer w10: R122.2@485,1592.5 644.5,1752 1471,1752 1523,1804 1523,3020.24 Q20.3@1471.24,3072
NetQ24_1: Q24.1 Q24.2 Q24.5 Q24.6 R127.2 R128.2 | length 202.9
  Top Layer w20: Q24.2@1379,1639 Q24.1@1416.4,1639 1468,1639 1473.03,1633.97 R127.2@1473.03,1593.92
  Top Layer w30: Q24.6@1415.74,1536.64 1437.38,1515 R128.2@1473.49,1515
  other v1: 1511,1424 1511,1449 1511,1474 1511,1499 1511,1524 1511,1549 1511,1574 1511,1599 1511,1624
NetQ28_3: Q28.3 R135.1 | length 44.1
  Top Layer w18: Q28.3@2028,857.6 R135.1@2072.1,857.6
